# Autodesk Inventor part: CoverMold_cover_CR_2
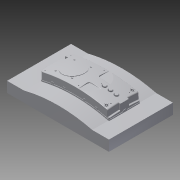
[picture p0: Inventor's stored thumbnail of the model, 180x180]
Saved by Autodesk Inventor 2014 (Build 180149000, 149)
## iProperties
Created: 2009-12
Part Number: CoverMold_cover_CR_2
Document SubType Name: Modeling
Designer: gaom
Density: 1 g/cm^3
Material: Generic
Appearance: Default
Author: gaom
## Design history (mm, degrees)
node "CoverMold_cover_CR_Base"
feature "Solid1::CoverMold_cover_CR_Base"
tag "TaggingFeature1"
body "Solid1"
